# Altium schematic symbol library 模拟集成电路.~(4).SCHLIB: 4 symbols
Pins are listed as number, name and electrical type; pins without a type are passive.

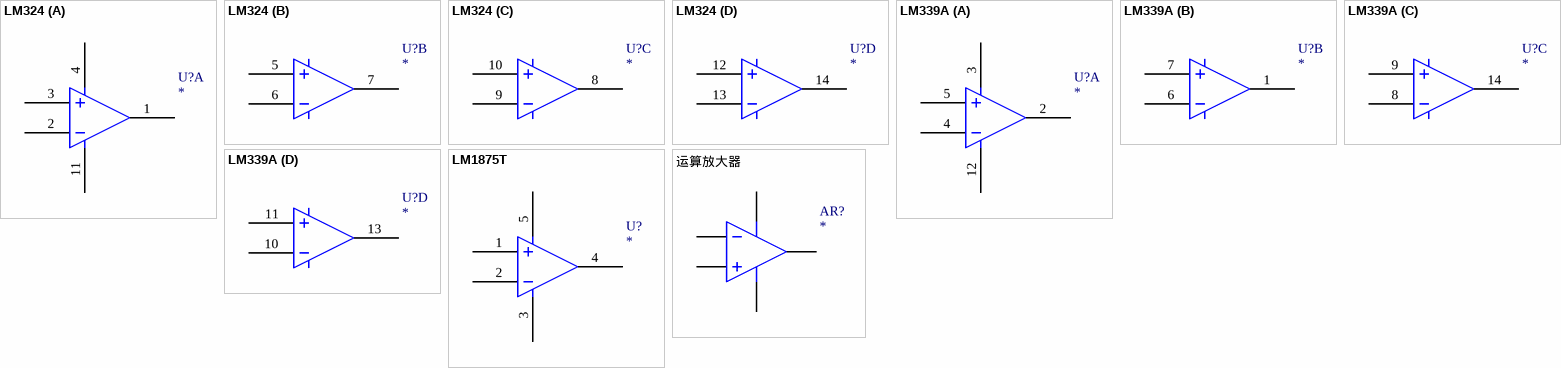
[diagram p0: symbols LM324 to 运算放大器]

## LM324
designator U?
footprint DIP-14
part A pins: 1, 2, 3, 4, 11
part B pins: 5, 6, 7
part C pins: 8, 9, 10
part D pins: 12, 13, 14

## LM339A
designator U?
footprint DIP-14
part A pins: 2, 3, 4, 5, 12
part B pins: 1, 6, 7
part C pins: 8, 9, 14
part D pins: 10, 11, 13

## LM1875T
designator U?
footprint TO-220
footprint TO-220-5
pins: 1, 2, 3, 4, 5

## 运算放大器
designator AR?
Operational Amplifier
footprint DIP-8N
pins: 1 OUT, 2 IN-, 3 IN+, 4 V+, 8 V-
